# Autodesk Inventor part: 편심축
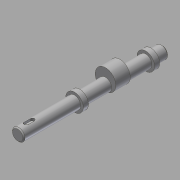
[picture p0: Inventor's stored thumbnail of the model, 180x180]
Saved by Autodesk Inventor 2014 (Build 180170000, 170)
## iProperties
Created: 2016-02
Part Number: 편심축
Material: 강철, 연강
Document SubType Name: Modeling
Designer: mduedu
Density: 1 g/cm^3
Appearance: Steel
Author: mduedu
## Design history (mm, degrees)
sketch "스케치1"
  geometry: C1 r 6 at (0, 0); 1 further point
  constraints: 1 centre point, 1 coincident
  dimensions: "d0" = 12 diameter of C1
extrude "돌출1" new body sketch "스케치1" distance "d1" = 140; taper "d2" = 0 deg
chamfer "모따기1" distance "d3" = 1; stored, may be unused: second distance "d4" = 2, angle "d5" = 45 deg
node "작업 평면1"
sketch "스케치2"
  geometry: C1 r 10 at (0, 4); C2 r 6 at (0, 0) reference; 1 further point
  constraints: 1 centre point, 1 tangent, 1 vertical alignment
  dimensions: "d7" = 20 diameter of C1
extrude "돌출2" join sketch "스케치2" stored distance "d8" = 14; taper "d9" = 0 deg
node "작업 평면2"
sketch "스케치3"
  geometry: C1 r 8.5 at (0, 0); 1 further point
  constraints: 1 centre point, 1 coincident
  dimensions: "d12" = 17 diameter of C1
extrude "돌출3" join sketch "스케치3" distance "d13" = 5; taper "d14" = 0 deg
node "작업 평면3"
sketch "스케치4"
  geometry: L1 (-5, 140)-(5, 140) reference; L2 (0, 140)-(0, 0); L3 (-2, 132)-(-2, 126); L4 (2, 126)-(2, 132); A1 r 2 centre (0, 132) between (2, 132) and (-2, 132); A2 r 2 centre (0, 126) between (-2, 126) and (2, 126)
  constraints: 6 end point, 4 point on circle, 4 tangent, 2 centre point, 2 point on line, 1 midpoint, 1 parallel, 1 perpendicular
  dimensions: "d15" = 4 distance between parallel lines of L3 L4; "d17" = 6 distance edge to line of A1 L1; "d18" = 10 dimension on A2 A1
extrude "돌출4" cut sketch "스케치4" distance "d19" = 2.5; taper "d20" = 0 deg
sketch "스케치5"
  geometry: L1 (6, 55)-(6, 139) reference; L2 (-6, 55)-(-6, 139) reference; L3 (6, 115)-(-6, 115); L4 (-5, 140)-(5, 140) reference; L5 (6, 116.5)-(4.5, 115); L6 (6, 116.5)-(6, 115); L7 (4.5, 115)-(6, 115); 1 further point
  constraints: 8 end point, 4 point on line, 2 collinear, 1 perpendicular
  dimensions: "d21" = 25 distance between parallel lines of L3 L4; "d22" = 3 diameter of L5.start L3; "d24" = 45 deg angle of L3 L5
revolve "회전1" sketch "스케치5" stored, may be unused: angle "d25" = 90 deg
sketch "스케치6"
  geometry: L1 (6, 116.5)-(4.5, 115) reference; L2 (6, 113.5)-(4.5, 115) reference; 2 further points
  constraints: 1 coincident
node "작업 평면4"
sketch "스케치7"
  geometry: C1 r 8.5 at (0, -4); 1 further point
  constraints: 1 centre point, 1 coincident
  dimensions: "d27" = 17 diameter of C1
extrude "돌출5" join sketch "스케치7" distance "d29" = 5; taper "d30" = 0 deg
node "솔리드1"
other parameters: "d6" = -48, "d11" = -11
